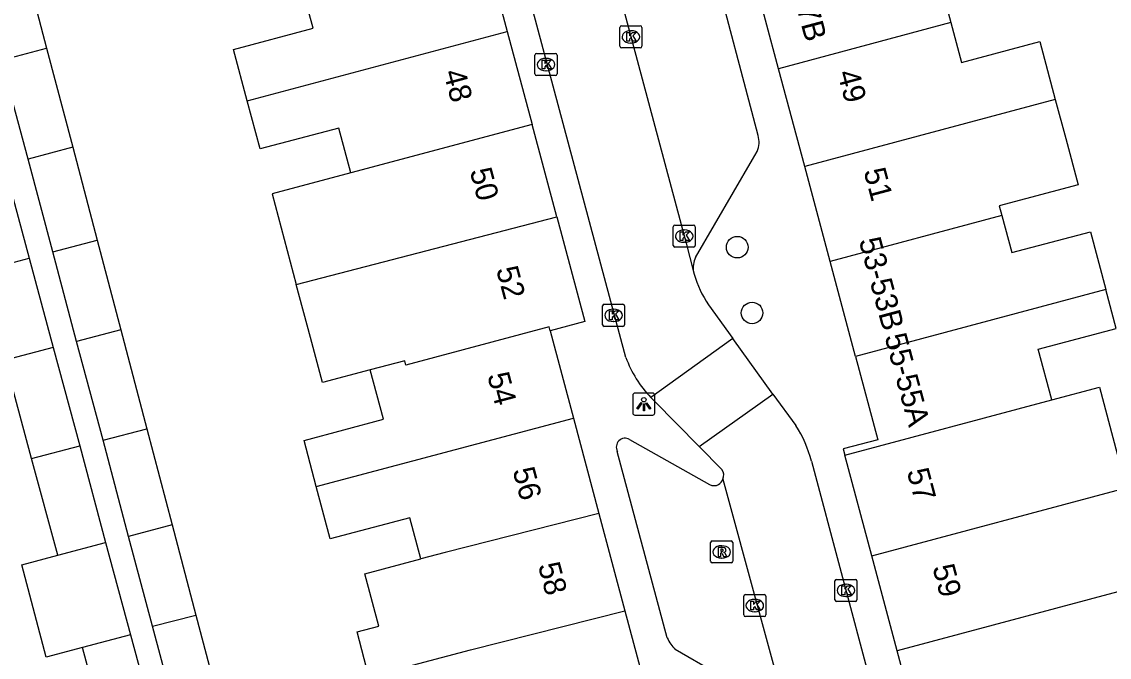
# Model space of a CAD drawing. Extents: x 162542 to 163144, y 380786 to 381511.
# Drawn here: x 162921.91 to 162971.22, y 380940.01 to 380968.84 of the extents above; entities that cross this region are included whole.
import ezdxf

# ---------------------------------------------------------------- set-up
doc = ezdxf.new("R2010")
doc.units = 0
for name, color, linetype in [('IMGEO_Boom', 7, 'Continuous'), ('IMGEO_Kolk', 7, 'Continuous'), ('IMGEO_Lichtpunt', 7, 'Continuous'), ('IMGEO_Pand', 7, 'Continuous'), ('IMGEO_Pand_nummerreeks', 7, 'Continuous'), ('IMGEO_Rijbaan_lokaal_open', 7, 'Continuous'), ('IMGEO_Rioolput', 7, 'Continuous'), ('IMGEO_Voetpad_open', 7, 'Continuous')]:
    doc.layers.add(name, color=color, linetype=linetype)

msp = doc.modelspace()

# ---------------------------------------------------------------- linework, layer by layer
at = {"layer": 'IMGEO_Boom'}
for centre in [(162954.351, 380958.615), (162955.023, 380955.633)]:
    msp.add_circle(centre, 0.489, dxfattribs=at)
at = {"layer": 'IMGEO_Kolk'}
for p, q in [((162949.029, 380967.731), (162949.029, 380968.583)), ((162949.104, 380968.657), (162949.956, 380968.657)), ((162950.03, 380968.583), (162950.03, 380967.731)), ((162949.517, 380968.437), (162949.542, 380968.437)), ((162949.956, 380967.657), (162949.104, 380967.657)), ((162949.54, 380967.877), (162949.515, 380967.877)), ((162945.181, 380966.476), (162945.181, 380967.328)), ((162945.256, 380967.402), (162946.108, 380967.402)), ((162945.669, 380967.182), (162945.694, 380967.182)), ((162946.182, 380967.328), (162946.182, 380966.476)), ((162945.692, 380966.622), (162945.667, 380966.622)), ((162946.108, 380966.402), (162945.256, 380966.402)), ((162951.447, 380958.692), (162951.447, 380959.544)), ((162951.522, 380959.618), (162952.374, 380959.618)), ((162951.935, 380959.398), (162951.96, 380959.398)), ((162952.448, 380959.544), (162952.448, 380958.692)), ((162951.958, 380958.838), (162951.933, 380958.838)), ((162952.374, 380958.618), (162951.522, 380958.618)), ((162948.244, 380955.098), (162948.244, 380955.95)), ((162948.319, 380956.024), (162949.171, 380956.024)), ((162948.732, 380955.804), (162948.757, 380955.804)), ((162949.245, 380955.95), (162949.245, 380955.098)), ((162949.171, 380955.024), (162948.319, 380955.024)), ((162948.755, 380955.244), (162948.73, 380955.244)), ((162958.78, 380942.622), (162958.78, 380943.474)), ((162958.855, 380943.548), (162959.707, 380943.548)), ((162959.781, 380943.474), (162959.781, 380942.622)), ((162959.268, 380943.328), (162959.293, 380943.328)), ((162954.647, 380941.933), (162954.647, 380942.785)), ((162954.722, 380942.859), (162955.574, 380942.859)), ((162955.135, 380942.639), (162955.16, 380942.639)), ((162955.648, 380942.785), (162955.648, 380941.933)), ((162959.707, 380942.548), (162958.855, 380942.548)), ((162959.291, 380942.768), (162959.266, 380942.768)), ((162955.158, 380942.079), (162955.133, 380942.079)), ((162955.574, 380941.859), (162954.722, 380941.859))]:
    msp.add_line(p, q, dxfattribs=at)
for points in [[(162949.029, 380967.731), (162949.029, 380968.583)], [(162949.104, 380968.657), (162949.956, 380968.657)], [(162950.03, 380968.583), (162950.03, 380967.731)], [(162949.35, 380968.357), (162949.473, 380968.357), (162949.473, 380968.206), (162949.603, 380968.357), (162949.767, 380968.357), (162949.621, 380968.206), (162949.774, 380967.957), (162949.622, 380967.957), (162949.537, 380968.121), (162949.473, 380968.054), (162949.473, 380967.957), (162949.35, 380967.957), (162949.35, 380968.357)], [(162949.956, 380967.657), (162949.104, 380967.657)], [(162945.181, 380966.476), (162945.181, 380967.328)], [(162945.256, 380967.402), (162946.108, 380967.402)], [(162945.502, 380967.102), (162945.625, 380967.102), (162945.625, 380966.951), (162945.755, 380967.102), (162945.919, 380967.102), (162945.773, 380966.951), (162945.926, 380966.702), (162945.774, 380966.702), (162945.689, 380966.866), (162945.625, 380966.799), (162945.625, 380966.702), (162945.502, 380966.702), (162945.502, 380967.102)], [(162946.182, 380967.328), (162946.182, 380966.476)], [(162946.108, 380966.402), (162945.256, 380966.402)], [(162951.447, 380958.692), (162951.447, 380959.544)], [(162951.522, 380959.618), (162952.374, 380959.618)], [(162951.768, 380959.318), (162951.891, 380959.318), (162951.891, 380959.167), (162952.021, 380959.318), (162952.185, 380959.318), (162952.039, 380959.167), (162952.192, 380958.918), (162952.04, 380958.918), (162951.955, 380959.082), (162951.891, 380959.015), (162951.891, 380958.918), (162951.768, 380958.918), (162951.768, 380959.318)], [(162952.448, 380959.544), (162952.448, 380958.692)], [(162952.374, 380958.618), (162951.522, 380958.618)], [(162948.244, 380955.098), (162948.244, 380955.95)], [(162948.319, 380956.024), (162949.171, 380956.024)], [(162949.245, 380955.95), (162949.245, 380955.098)], [(162948.565, 380955.724), (162948.688, 380955.724), (162948.688, 380955.573), (162948.818, 380955.724), (162948.982, 380955.724), (162948.836, 380955.573), (162948.989, 380955.324), (162948.837, 380955.324), (162948.752, 380955.488), (162948.688, 380955.421), (162948.688, 380955.324), (162948.565, 380955.324), (162948.565, 380955.724)], [(162949.171, 380955.024), (162948.319, 380955.024)], [(162958.78, 380942.622), (162958.78, 380943.474)], [(162958.855, 380943.548), (162959.707, 380943.548)], [(162959.781, 380943.474), (162959.781, 380942.622)], [(162959.101, 380943.248), (162959.224, 380943.248), (162959.224, 380943.097), (162959.354, 380943.248), (162959.518, 380943.248), (162959.372, 380943.097), (162959.525, 380942.848), (162959.373, 380942.848), (162959.288, 380943.012), (162959.224, 380942.945), (162959.224, 380942.848), (162959.101, 380942.848), (162959.101, 380943.248)], [(162954.647, 380941.933), (162954.647, 380942.785)], [(162954.722, 380942.859), (162955.574, 380942.859)], [(162954.968, 380942.559), (162955.091, 380942.559), (162955.091, 380942.408), (162955.221, 380942.559), (162955.385, 380942.559), (162955.239, 380942.408), (162955.392, 380942.159), (162955.24, 380942.159), (162955.155, 380942.323), (162955.091, 380942.256), (162955.091, 380942.159), (162954.968, 380942.159), (162954.968, 380942.559)], [(162955.648, 380942.785), (162955.648, 380941.933)], [(162959.707, 380942.548), (162958.855, 380942.548)], [(162955.574, 380941.859), (162954.722, 380941.859)]]:
    msp.add_lwpolyline(points, dxfattribs=at)
for centre, start, end in [((162949.106, 380968.581), 91.552, 178.448), ((162949.106, 380968.581), 91.552, 178.448), ((162949.954, 380968.581), 1.552, 88.448), ((162949.954, 380968.581), 1.552, 88.448), ((162949.106, 380967.733), 181.552, 268.448), ((162949.106, 380967.733), 181.552, 268.448), ((162949.954, 380967.733), 271.552, 358.448), ((162949.954, 380967.733), 271.552, 358.448), ((162945.258, 380967.326), 91.552, 178.448), ((162945.258, 380967.326), 91.552, 178.448), ((162946.106, 380967.326), 1.552, 88.448), ((162946.106, 380967.326), 1.552, 88.448), ((162945.258, 380966.478), 181.552, 268.448), ((162945.258, 380966.478), 181.552, 268.448), ((162946.106, 380966.478), 271.552, 358.448), ((162946.106, 380966.478), 271.552, 358.448), ((162951.524, 380959.542), 91.552, 178.448), ((162951.524, 380959.542), 91.552, 178.448), ((162952.372, 380959.542), 1.552, 88.448), ((162952.372, 380959.542), 1.552, 88.448), ((162951.524, 380958.694), 181.552, 268.448), ((162951.524, 380958.694), 181.552, 268.448), ((162952.372, 380958.694), 271.552, 358.448), ((162952.372, 380958.694), 271.552, 358.448), ((162948.321, 380955.948), 91.552, 178.448), ((162948.321, 380955.948), 91.552, 178.448), ((162949.169, 380955.948), 1.552, 88.448), ((162949.169, 380955.948), 1.552, 88.448), ((162948.321, 380955.1), 181.552, 268.448), ((162948.321, 380955.1), 181.552, 268.448), ((162949.169, 380955.1), 271.552, 358.448), ((162949.169, 380955.1), 271.552, 358.448), ((162958.857, 380943.472), 91.552, 178.448), ((162958.857, 380943.472), 91.552, 178.448), ((162959.705, 380943.472), 1.552, 88.448), ((162959.705, 380943.472), 1.552, 88.448), ((162954.724, 380942.783), 91.552, 178.448), ((162954.724, 380942.783), 91.552, 178.448), ((162955.572, 380942.783), 1.552, 88.448), ((162955.572, 380942.783), 1.552, 88.448), ((162958.857, 380942.624), 181.552, 268.448), ((162958.857, 380942.624), 181.552, 268.448), ((162959.705, 380942.624), 271.552, 358.448), ((162959.705, 380942.624), 271.552, 358.448), ((162954.724, 380941.935), 181.552, 268.448), ((162954.724, 380941.935), 181.552, 268.448), ((162955.572, 380941.935), 271.552, 358.448), ((162955.572, 380941.935), 271.552, 358.448)]:
    msp.add_arc(centre, 0.0765, start, end, dxfattribs=at)
for centre, major_axis, ratio, start_param, end_param in [((162949.516, 380968.157), (-0.387, 0.002), 0.722429, 4.712389, 7.853982), ((162949.541, 380968.157), (-0.39, 0.002), 0.717154, 1.570796, 4.712389), ((162945.668, 380966.902), (-0.387, 0.002), 0.722429, 4.712389, 7.853982), ((162945.693, 380966.902), (-0.39, 0.002), 0.717154, 1.570796, 4.712389), ((162951.934, 380959.118), (-0.387, 0.002), 0.722429, 4.712389, 7.853982), ((162951.959, 380959.118), (-0.39, 0.002), 0.717154, 1.570796, 4.712389), ((162948.731, 380955.524), (-0.387, 0.002), 0.722429, 4.712389, 7.853982), ((162948.756, 380955.524), (-0.39, 0.002), 0.717154, 1.570796, 4.712389), ((162959.267, 380943.048), (-0.387, 0.002), 0.722429, 4.712389, 7.853982), ((162959.292, 380943.048), (-0.39, 0.002), 0.717154, 1.570796, 4.712389), ((162955.134, 380942.359), (-0.387, 0.002), 0.722429, 4.712389, 7.853982), ((162955.159, 380942.359), (-0.39, 0.002), 0.717154, 1.570796, 4.712389)]:
    msp.add_ellipse(centre, major_axis=major_axis, ratio=ratio, start_param=start_param, end_param=end_param, dxfattribs=at)
at = {"layer": 'IMGEO_Lichtpunt'}
for p, q in [((162949.618, 380951.9), (162949.618, 380951.093)), ((162949.618, 380951.9), (162949.618, 380951.093)), ((162950.52, 380951.995), (162949.712, 380951.995)), ((162950.52, 380951.995), (162949.712, 380951.995)), ((162950.614, 380951.093), (162950.614, 380951.9)), ((162950.614, 380951.093), (162950.614, 380951.9)), ((162949.712, 380950.999), (162950.52, 380950.999)), ((162949.712, 380950.999), (162950.52, 380950.999))]:
    msp.add_line(p, q, dxfattribs=at)
for points in [[(162949.992, 380951.564), (162950.031, 380951.536), (162949.843, 380951.274), (162949.805, 380951.301), (162949.992, 380951.564)], [(162950.094, 380951.516), (162950.141, 380951.516), (162950.141, 380951.194), (162950.094, 380951.194), (162950.094, 380951.516)], [(162950.204, 380951.536), (162950.242, 380951.563), (162950.429, 380951.301), (162950.39, 380951.273), (162950.204, 380951.536)]]:
    msp.add_lwpolyline(points, dxfattribs=at)
msp.add_circle((162950.117, 380951.698), 0.0994, dxfattribs=at)
for centre, start, end in [((162949.712, 380951.9), 90, 180), ((162949.712, 380951.9), 90, 180), ((162950.52, 380951.9), 0, 90), ((162950.52, 380951.9), 0, 90), ((162949.712, 380951.093), 180, 270), ((162949.712, 380951.093), 180, 270), ((162950.52, 380951.093), 270, 0), ((162950.52, 380951.093), 270, 360)]:
    msp.add_arc(centre, 0.0946, start, end, dxfattribs=at)
at = {"layer": 'IMGEO_Pand'}
for points in [[(162966.413, 380974.183), (162966.943, 380972.196), (162963.39, 380971.248), (162964.042, 380968.803)], [(162942.72, 380972.887), (162943.922, 380968.397)], [(162921.91, 380971.941), (162923.04, 380967.646)], [(162956.224, 380966.712), (162955.04, 380971.141)], [(162932.139, 380965.259), (162931.518, 380967.588), (162935.118, 380968.549), (162934.542, 380970.709)], [(162964.042, 380968.803), (162956.224, 380966.712)], [(162964.042, 380968.803), (162964.523, 380966.999), (162968.072, 380967.945), (162968.772, 380965.322)], [(162932.139, 380965.259), (162943.922, 380968.397)], [(162943.922, 380968.397), (162945.051, 380964.179)], [(162920.997, 380967.102), (162923.04, 380967.646)], [(162923.04, 380967.646), (162924.223, 380963.151)], [(162922.195, 380962.611), (162920.997, 380967.102)], [(162957.409, 380962.283), (162956.224, 380966.712)], [(162936.828, 380961.994), (162936.287, 380964.021), (162932.723, 380963.07), (162932.139, 380965.259)], [(162968.772, 380965.322), (162957.409, 380962.283)], [(162968.772, 380965.322), (162969.246, 380963.543), (162969.804, 380961.448), (162966.233, 380960.497), (162966.351, 380960.053)], [(162945.051, 380964.179), (162936.828, 380961.994)], [(162946.17, 380959.997), (162945.051, 380964.179)], [(162924.223, 380963.151), (162922.195, 380962.611)], [(162924.223, 380963.151), (162925.332, 380958.939)], [(162921.081, 380962.458), (162922.248, 380958.118)], [(162923.316, 380958.404), (162922.195, 380962.611)], [(162958.562, 380957.97), (162957.409, 380962.283)], [(162936.828, 380961.994), (162933.259, 380961.039), (162934.358, 380956.928)], [(162934.358, 380956.928), (162946.17, 380959.997)], [(162946.17, 380959.997), (162947.441, 380955.248), (162945.866, 380954.827)], [(162966.351, 380960.053), (162958.562, 380957.97)], [(162966.351, 380960.053), (162966.8, 380958.369), (162970.363, 380959.32), (162971.064, 380956.693)], [(162923.316, 380958.404), (162925.332, 380958.939)], [(162925.332, 380958.939), (162926.405, 380954.862)], [(162924.4, 380954.341), (162923.316, 380958.404)], [(162917.929, 380956.97), (162922.248, 380958.118)], [(162922.248, 380958.118), (162923.338, 380954.064)], [(162959.715, 380953.658), (162958.562, 380957.97)], [(162937.715, 380953.047), (162935.545, 380952.476), (162935, 380954.519), (162934.358, 380956.928)], [(162971.064, 380956.693), (162959.715, 380953.658)], [(162968.612, 380951.687), (162967.997, 380953.99), (162971.533, 380954.934), (162971.064, 380956.693)], [(162926.405, 380954.862), (162924.4, 380954.341)], [(162926.405, 380954.862), (162927.584, 380950.38)], [(162945.866, 380954.827), (162945.819, 380955.004), (162939.326, 380953.271), (162939.276, 380953.458), (162937.715, 380953.047)], [(162945.866, 380954.827), (162946.925, 380950.857)], [(162925.596, 380949.856), (162924.4, 380954.341)], [(162923.338, 380954.064), (162921.158, 380953.498)], [(162923.338, 380954.064), (162924.539, 380949.598)], [(162922.36, 380949.028), (162921.158, 380953.498)], [(162959.715, 380953.658), (162960.725, 380949.882), (162959.154, 380949.463), (162959.229, 380949.183)], [(162935.267, 380947.76), (162934.709, 380949.852), (162938.311, 380950.813), (162937.715, 380953.047)], [(162968.612, 380951.687), (162970.771, 380952.263), (162971.988, 380947.7)], [(162959.229, 380949.183), (162968.612, 380951.687)], [(162935.267, 380947.76), (162946.925, 380950.857)], [(162946.925, 380950.857), (162948.08, 380946.529)], [(162925.596, 380949.856), (162927.584, 380950.38)], [(162927.584, 380950.38), (162928.73, 380946.024)], [(162926.758, 380945.499), (162925.596, 380949.856)], [(162922.36, 380949.028), (162924.539, 380949.598)], [(162924.539, 380949.598), (162925.716, 380945.222)], [(162923.54, 380944.644), (162922.36, 380949.028)], [(162960.448, 380944.613), (162959.229, 380949.183)], [(162940.002, 380944.475), (162939.505, 380946.341), (162935.902, 380945.38), (162935.267, 380947.76)], [(162960.448, 380944.613), (162971.988, 380947.7)], [(162948.08, 380946.529), (162941.116, 380944.772), (162940.002, 380944.475)], [(162948.08, 380946.529), (162949.255, 380942.123)], [(162928.73, 380946.024), (162926.758, 380945.499)], [(162928.73, 380946.024), (162929.81, 380941.92)], [(162927.845, 380941.424), (162926.758, 380945.499)], [(162923.54, 380944.644), (162925.716, 380945.222)], [(162925.716, 380945.222), (162926.844, 380941.026)], [(162924.666, 380940.457), (162923.015, 380940.026), (162921.921, 380944.214), (162923.54, 380944.644)], [(162937.644, 380939.132), (162937.118, 380941.161), (162938.107, 380941.425), (162937.472, 380943.802), (162940.002, 380944.475)], [(162961.599, 380940.299), (162960.448, 380944.613)], [(162973.14, 380943.385), (162961.599, 380940.299)], [(162937.644, 380939.132), (162938.08, 380939.246), (162942.26, 380940.359), (162949.255, 380942.123)], [(162949.255, 380942.123), (162950.43, 380937.718)], [(162927.845, 380941.424), (162929.81, 380941.92)], [(162929.81, 380941.92), (162931.009, 380937.363)], [(162926.844, 380941.026), (162924.666, 380940.457)], [(162926.844, 380941.026), (162928.029, 380936.623)], [(162929.066, 380936.846), (162927.845, 380941.424)], [(162925.856, 380936.055), (162923.774, 380935.511), (162923.211, 380937.718), (162925.27, 380938.211), (162924.666, 380940.457)], [(162962.749, 380935.986), (162961.599, 380940.299)]]:
    msp.add_lwpolyline(points, dxfattribs=at)
at = {"layer": 'IMGEO_Rijbaan_lokaal_open'}
for points in [[(162949.301, 380953.613), (162937.085, 380999.244), (162935.911, 381003.519), (162933.706, 381011.552), (162932.068, 381018.083)], [(162937.182, 381014.315), (162952.035, 380958.794), (162952.371, 380957.505)], [(162952.371, 380957.505), (162952.401, 380957.391)], [(162953.05, 380956.004), (162954.148, 380954.475)], [(162954.148, 380954.475), (162950.434, 380951.798)], [(162955.963, 380951.953), (162954.148, 380954.475)], [(162952.632, 380949.57), (162955.963, 380951.953)], [(162955.963, 380951.953), (162957.014, 380950.527)], [(162950.434, 380951.798), (162950.512, 380951.718), (162950.591, 380951.639), (162952.632, 380949.57)], [(162953.655, 380948.534), (162952.632, 380949.57)], [(162957.72, 380948.914), (162963.098, 380928.709)], [(162953.706, 380948.086), (162958.51, 380930.441), (162958.873, 380929.023), (162959.022, 380928.201), (162959.089, 380927.574), (162959.887, 380921.279)]]:
    msp.add_lwpolyline(points, dxfattribs=at)
for centre, radius, start, end in [((162956.993, 380958.694), 4.774, 195.8461, 214.3052), ((162954.302, 380955.474), 5.336, 200.4087, 223.5396), ((162952.034, 380947.386), 5.887, 15.0386, 32.2388), ((162953.264, 380948.263), 0.476, 338.2047, 34.7844)]:
    msp.add_arc(centre, radius, start, end, dxfattribs=at)
at = {"layer": 'IMGEO_Rioolput'}
for p, q in [((162953.146, 380944.366), (162953.146, 380945.218)), ((162953.221, 380945.292), (162954.073, 380945.292)), ((162953.634, 380945.072), (162953.659, 380945.072)), ((162954.147, 380945.218), (162954.147, 380944.366)), ((162953.657, 380944.512), (162953.632, 380944.512)), ((162954.073, 380944.292), (162953.221, 380944.292))]:
    msp.add_line(p, q, dxfattribs=at)
for points in [[(162953.146, 380944.366), (162953.146, 380945.218)], [(162953.221, 380945.292), (162954.073, 380945.292)], [(162953.735, 380944.99), (162953.483, 380944.992), (162953.483, 380944.592)], [(162953.661, 380944.911), (162953.607, 380944.911), (162953.607, 380944.83)], [(162954.147, 380945.218), (162954.147, 380944.366)], [(162953.483, 380944.592), (162953.607, 380944.592), (162953.607, 380944.754), (162953.618, 380944.754)], [(162953.607, 380944.83), (162953.659, 380944.83)], [(162953.665, 380944.725), (162953.736, 380944.592), (162953.876, 380944.592), (162953.811, 380944.718)], [(162954.073, 380944.292), (162953.221, 380944.292)]]:
    msp.add_lwpolyline(points, dxfattribs=at)
for centre, radius, start, end in [((162953.223, 380945.216), 0.0765, 91.552, 178.448), ((162953.223, 380945.216), 0.0765, 91.552, 178.448), ((162953.667, 380944.815), 0.0964, 77.0061, 93.1865), ((162953.681, 380944.872), 0.0378, 276.6634, 79.6772), ((162953.734, 380944.88), 0.109, 350.3612, 89.416), ((162954.071, 380945.216), 0.0765, 1.552, 88.448), ((162954.071, 380945.216), 0.0765, 1.552, 88.448), ((162953.617, 380944.701), 0.0533, 26.0293, 88.6989), ((162953.643, 380945.019), 0.19, 274.7715, 282.9687), ((162953.732, 380944.88), 0.112, 277.5842, 350.9817), ((162953.716, 380944.665), 0.108, 29.5134, 73.7905), ((162953.223, 380944.368), 0.0765, 181.552, 268.448), ((162953.223, 380944.368), 0.0765, 181.552, 268.448), ((162954.071, 380944.368), 0.0765, 271.552, 358.448), ((162954.071, 380944.368), 0.0765, 271.552, 358.448)]:
    msp.add_arc(centre, radius, start, end, dxfattribs=at)
for centre, major_axis, ratio, start_param, end_param in [((162953.633, 380944.792), (-0.387, 0.002), 0.722429, 4.712389, 7.853982), ((162953.658, 380944.792), (-0.39, 0.002), 0.717154, 1.570796, 4.712389)]:
    msp.add_ellipse(centre, major_axis=major_axis, ratio=ratio, start_param=start_param, end_param=end_param, dxfattribs=at)
at = {"layer": 'IMGEO_Voetpad_open'}
for points in [[(162955.294, 380963.679), (162953.201, 380971.654), (162953.049, 380972.123)], [(162952.463, 380958.155), (162955.037, 380962.597), (162955.257, 380962.961)], [(162949.472, 380949.897), (162953.1, 380947.851)], [(162951.181, 380940.891), (162948.915, 380949.353)], [(162956.13, 380937.703), (162955.201, 380938.254), (162951.543, 380940.365)]]:
    msp.add_lwpolyline(points, dxfattribs=at)
for centre, radius, start, end in [((162954.365, 380963.367), 0.98, 335.5342, 18.5659), ((162953.35, 380957.698), 0.997, 152.7313, 191.1566), ((162949.27, 380949.546), 0.404, 60.0682, 208.5788), ((162953.258, 380948.271), 0.485, 300.5374, 337.6151), ((162953.3, 380948.21), 0.411, 240.8809, 299.6863), ((162952.545, 380941.442), 1.471, 201.9985, 227.074)]:
    msp.add_arc(centre, radius, start, end, dxfattribs=at)

# ---------------------------------------------------------------- texts
at = {"layer": 'IMGEO_Pand_nummerreeks'}
for s, rotation, p in [('47-47B', 284.9654, (162956.352, 380972.041)), ('48', 284.983, (162941.021, 380966.549)), ('49', 284.9718, (162958.883, 380966.524)), ('50', 284.9826, (162942.218, 380962.079)), ('51', 284.9712, (162960.074, 380962.074)), ('53-53B', 284.9712, (162959.859, 380958.925)), ('52', 284.983, (162943.412, 380957.614)), ('55-55A', 284.9769, (162961.023, 380954.572)), ('54', 284.9366, (162943.011, 380952.804)), ('56', 284.9366, (162944.16, 380948.497)), ('57', 284.9332, (162962.033, 380948.453)), ('58', 284.9366, (162945.31, 380944.186)), ('59', 284.9332, (162963.195, 380944.097))]:
    msp.add_text(s, height=1, rotation=rotation, dxfattribs=at).set_placement(p)

doc.saveas('drawing.dxf')
